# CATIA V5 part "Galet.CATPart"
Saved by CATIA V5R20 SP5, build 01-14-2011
Part number: Galet
Bounding box of the stored display mesh (mm): x 0 to 5, y -5 to 5, z -4.99 to 4.99
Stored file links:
  D:\Dropbox\IAO_2011\MMS_GR3\IAO_2011_1475_rguinot\IAO\IAO_2011_1475_rguinot\Galet.CATPart
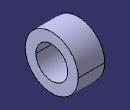
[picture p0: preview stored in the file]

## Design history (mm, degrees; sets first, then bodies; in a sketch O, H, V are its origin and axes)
Body1 (main body)
  Sketch1 on yz-plane, origin (0, 0, 0), H (0, 1, 0), V (0, 0, 1)
    circle A1 centre (0, 0) radius 5
    circle A2 centre (0, 0) radius 3
    radius A2 = 3
    radius A1 = 5
  Pad1: profile Sketch1, direction (1, 0, 0), length 5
